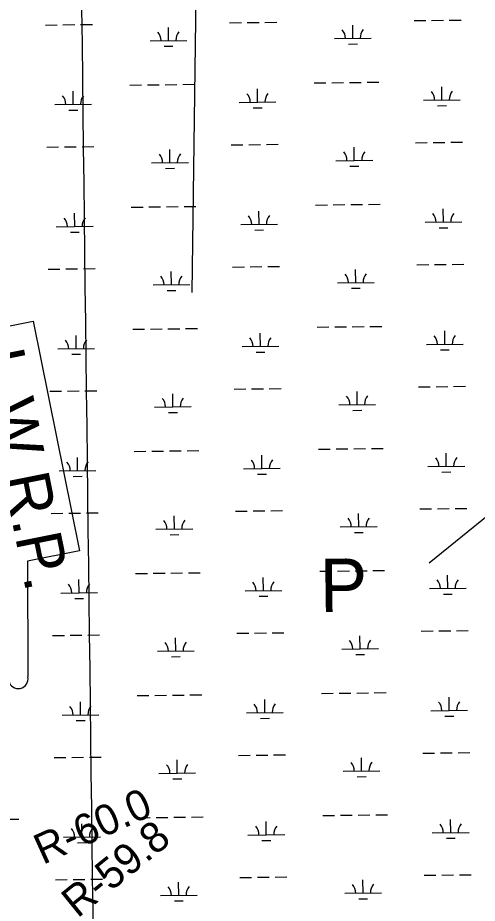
# Model space of a CAD drawing. Extents: x 3694830 to 3732949, y 415201 to 440970.
# Drawn here: x 3720008 to 3721259, y 422124 to 424536 of the extents above; entities that cross this region are included whole.
import ezdxf

# ---------------------------------------------------------------- set-up
doc = ezdxf.new("R2010")
doc.units = 0
for name, color, linetype in [('V-GRID-MAJR', 7, 'Continuous'), ('V-RIVR-RANG-IDEN', 7, 'Continuous'), ('V-TOPO-GNAM-IDEN', 7, 'Continuous'), ('V-TOPO-SHOR', 7, 'Continuous'), ('V-TOPO-WATR-IDEN', 7, 'Continuous'), ('V-WETL-SWMP', 7, 'Continuous')]:
    doc.layers.add(name, color=color, linetype=linetype)

msp = doc.modelspace()

# ---------------------------------------------------------------- linework, layer by layer
at = {"layer": 'V-GRID-MAJR'}
msp.add_spline([(3720228.3, 420868.8), (3720155.2, 426926.1), (3720082, 432986.5), (3720008.8, 439046.9), (3720008.8, 439050)], degree=3, dxfattribs=at)
at = {"layer": 'V-TOPO-SHOR'}
for points in [[(3720482.9, 423787.9), (3720493.7, 424597.8), (3720504.4, 425159.5), (3720510.9, 425652.8), (3720512.1, 425923.1)], [(3721128.3, 423051.5), (3721324.1, 423210), (3721699, 423509.1), (3722006.1, 423752.1)]]:
    msp.add_lwpolyline(points, dxfattribs=at)
at = {"layer": 'V-TOPO-WATR-IDEN'}
msp.add_lwpolyline([(3719789.9, 423962.9), (3719908.3, 423681.4), (3720050.2, 423709.9), (3720175.9, 423083.8), (3720034, 423055.3), (3720035.4, 422740.2)], dxfattribs=at)
msp.add_arc((3720009.4, 422735), 26.5, 191.3511, 11.3511, dxfattribs=at)
at = {"layer": 'V-WETL-SWMP'}
for p, q in [((3720083, 424516.4), (3720115, 424516.8)), ((3720131, 424517), (3720163, 424517.4)), ((3720179, 424517.6), (3720211, 424518)), ((3720584.8, 424522.4), (3720616.8, 424522.8)), ((3720632.8, 424523), (3720664.8, 424523.4)), ((3720680.8, 424523.6), (3720712.8, 424523.9)), ((3720920.2, 424480), (3720919.8, 424516)), ((3721086.7, 424528.4), (3721118.7, 424528.8)), ((3721134.7, 424529), (3721166.7, 424529.4)), ((3721182.7, 424529.6), (3721214.7, 424529.9)), ((3720418.3, 424474), (3720417.9, 424510)), ((3720368.3, 424473.4), (3720468.3, 424474.6)), ((3720870.2, 424479.4), (3720970.2, 424480.6)), ((3720908.4, 424464.4), (3720932.4, 424464.7)), ((3720406.5, 424458.4), (3720430.5, 424458.7)), ((3720312.9, 424352.7), (3720344.9, 424353)), ((3720360.9, 424353.2), (3720392.9, 424353.6)), ((3720408.9, 424353.8), (3720440.9, 424354.2)), ((3720456.9, 424354.4), (3720488.9, 424354.8)), ((3720660.8, 424306.1), (3720660.4, 424342.1)), ((3720814.8, 424358.7), (3720846.8, 424359)), ((3720862.8, 424359.2), (3720894.8, 424359.6)), ((3720910.8, 424359.8), (3720942.8, 424360.2)), ((3720958.8, 424360.4), (3720990.8, 424360.8)), ((3721162.7, 424312.1), (3721162.3, 424348.1)), ((3720159, 424300.1), (3720158.5, 424336.1)), ((3720109, 424299.5), (3720209, 424300.7)), ((3720610.8, 424305.5), (3720710.8, 424306.7)), ((3721112.7, 424311.5), (3721212.7, 424312.7)), ((3721150.9, 424296.5), (3721174.9, 424296.8)), ((3720147.1, 424284.5), (3720171.1, 424284.8)), ((3720649, 424290.5), (3720673, 424290.8)), ((3721138.7, 424196.3), (3721170.7, 424196.7)), ((3721186.7, 424196.9), (3721218.7, 424197.3)), ((3720086.9, 424183.8), (3720118.9, 424184.2)), ((3720134.9, 424184.4), (3720166.9, 424184.7)), ((3720182.9, 424184.9), (3720214.9, 424185.3)), ((3720422.3, 424141.4), (3720421.9, 424177.3)), ((3720588.8, 424189.8), (3720620.8, 424190.2)), ((3720636.8, 424190.3), (3720668.8, 424190.7)), ((3720684.8, 424190.9), (3720716.8, 424191.3)), ((3720924.2, 424147.3), (3720923.7, 424183.3)), ((3721090.7, 424195.8), (3721122.7, 424196.1)), ((3720372.3, 424140.8), (3720472.3, 424141.9)), ((3720410.5, 424125.8), (3720434.5, 424126.1)), ((3720874.2, 424146.7), (3720974.2, 424147.9)), ((3720912.4, 424131.8), (3720936.4, 424132.1)), ((3720914.8, 424027.1), (3720946.8, 424027.5)), ((3720962.8, 424027.7), (3720994.8, 424028.1)), ((3720162.9, 423967.4), (3720162.5, 424003.4)), ((3720316.9, 424020), (3720348.9, 424020.4)), ((3720364.9, 424020.6), (3720396.9, 424021)), ((3720412.9, 424021.2), (3720444.9, 424021.5)), ((3720460.9, 424021.7), (3720492.9, 424022.1)), ((3720664.8, 423973.4), (3720664.4, 424009.4)), ((3720818.8, 424026), (3720850.8, 424026.4)), ((3720866.8, 424026.6), (3720898.8, 424027)), ((3721166.7, 423979.4), (3721166.2, 424015.4)), ((3721116.7, 423978.8), (3721216.7, 423980)), ((3720112.9, 423966.8), (3720212.9, 423968)), ((3720614.8, 423972.8), (3720714.8, 423974)), ((3720653, 423957.8), (3720677, 423958.1)), ((3721154.9, 423963.8), (3721178.9, 423964.1)), ((3720151.1, 423951.9), (3720175.1, 423952.1)), ((3720688.8, 423858.3), (3720720.8, 423858.6)), ((3721094.6, 423863.1), (3721126.6, 423863.5)), ((3721142.6, 423863.7), (3721174.6, 423864.1)), ((3721190.6, 423864.2), (3721222.6, 423864.6)), ((3720090.9, 423851.1), (3720122.9, 423851.5)), ((3720138.9, 423851.7), (3720170.9, 423852.1)), ((3720186.9, 423852.3), (3720218.9, 423852.7)), ((3720426.3, 423808.7), (3720425.8, 423844.7)), ((3720592.8, 423857.1), (3720624.8, 423857.5)), ((3720640.8, 423857.7), (3720672.8, 423858.1)), ((3720928.1, 423814.7), (3720927.7, 423850.7)), ((3720878.1, 423814.1), (3720978.1, 423815.3)), ((3720376.3, 423808.1), (3720476.3, 423809.3)), ((3720414.5, 423793.1), (3720438.5, 423793.4)), ((3720916.3, 423799.1), (3720940.3, 423799.4)), ((3720822.7, 423693.3), (3720854.7, 423693.7)), ((3720870.7, 423693.9), (3720902.7, 423694.3)), ((3720918.7, 423694.5), (3720950.7, 423694.9)), ((3720966.7, 423695.1), (3720998.7, 423695.4)), ((3720166.9, 423634.8), (3720166.5, 423670.8)), ((3720320.9, 423687.4), (3720352.9, 423687.7)), ((3720368.9, 423687.9), (3720400.9, 423688.3)), ((3720416.9, 423688.5), (3720448.9, 423688.9)), ((3720464.9, 423689.1), (3720496.9, 423689.5)), ((3720668.8, 423640.8), (3720668.3, 423676.8)), ((3721170.6, 423646.8), (3721170.2, 423682.8)), ((3721120.6, 423646.2), (3721220.6, 423647.3)), ((3720116.9, 423634.2), (3720216.9, 423635.4)), ((3720155.1, 423619.2), (3720179.1, 423619.5)), ((3720618.8, 423640.2), (3720718.8, 423641.4)), ((3720657, 423625.2), (3720680.9, 423625.5)), ((3721158.8, 423631.2), (3721182.8, 423631.5)), ((3720596.7, 423524.5), (3720628.7, 423524.8)), ((3720644.7, 423525), (3720676.7, 423525.4)), ((3720692.7, 423525.6), (3720724.7, 423526)), ((3721098.6, 423530.5), (3721130.6, 423530.8)), ((3721146.6, 423531), (3721178.6, 423531.4)), ((3721194.6, 423531.6), (3721226.6, 423532)), ((3720094.9, 423518.5), (3720126.9, 423518.9)), ((3720142.9, 423519.1), (3720174.9, 423519.4)), ((3720190.9, 423519.6), (3720222.9, 423520)), ((3720430.2, 423476), (3720429.8, 423512)), ((3720932.1, 423482), (3720931.7, 423518)), ((3720380.2, 423475.5), (3720480.2, 423476.6)), ((3720882.1, 423481.4), (3720982.1, 423482.6)), ((3720418.4, 423460.5), (3720442.4, 423460.8)), ((3720920.3, 423466.5), (3720944.3, 423466.7)), ((3720324.8, 423354.7), (3720356.8, 423355.1)), ((3720372.8, 423355.3), (3720404.8, 423355.7)), ((3720420.8, 423355.9), (3720452.8, 423356.2)), ((3720468.8, 423356.4), (3720500.8, 423356.8)), ((3720826.7, 423360.7), (3720858.7, 423361.1)), ((3720874.7, 423361.3), (3720906.7, 423361.7)), ((3720922.7, 423361.8), (3720954.7, 423362.2)), ((3720970.7, 423362.4), (3721002.7, 423362.8)), ((3720170.9, 423302.1), (3720170.4, 423338.1)), ((3720672.7, 423308.1), (3720672.3, 423344.1)), ((3721174.6, 423314.1), (3721174.2, 423350.1)), ((3720622.7, 423307.5), (3720722.7, 423308.7)), ((3721124.6, 423313.5), (3721224.6, 423314.7)), ((3720120.9, 423301.5), (3720220.9, 423302.7)), ((3720159, 423286.6), (3720183, 423286.8)), ((3720660.9, 423292.5), (3720684.9, 423292.8)), ((3721162.8, 423298.5), (3721186.8, 423298.8)), ((3720098.8, 423185.8), (3720130.8, 423186.2)), ((3720146.8, 423186.4), (3720178.8, 423186.8)), ((3720194.8, 423187), (3720226.8, 423187.4)), ((3720600.7, 423191.8), (3720632.7, 423192.2)), ((3720648.7, 423192.4), (3720680.7, 423192.8)), ((3720696.7, 423193), (3720728.7, 423193.3)), ((3720936.1, 423149.4), (3720935.7, 423185.4)), ((3721102.6, 423197.8), (3721134.6, 423198.2)), ((3721150.6, 423198.4), (3721182.6, 423198.8)), ((3721198.6, 423198.9), (3721230.6, 423199.3)), ((3720434.2, 423143.4), (3720433.8, 423179.4)), ((3720384.2, 423142.8), (3720484.2, 423144)), ((3720886.1, 423148.8), (3720986.1, 423150)), ((3720422.4, 423127.8), (3720446.4, 423128.1)), ((3720924.3, 423133.8), (3720948.3, 423134.1)), ((3720328.8, 423022.1), (3720360.8, 423022.4)), ((3720376.8, 423022.6), (3720408.8, 423023)), ((3720424.8, 423023.2), (3720456.8, 423023.6)), ((3720472.8, 423023.8), (3720504.8, 423024.2)), ((3720830.7, 423028), (3720862.7, 423028.4)), ((3720878.7, 423028.6), (3720910.7, 423029)), ((3720926.7, 423029.2), (3720958.7, 423029.6)), ((3720974.7, 423029.8), (3721006.7, 423030.1)), ((3721178.6, 422981.5), (3721178.1, 423017.4)), ((3720174.8, 422969.5), (3720174.4, 423005.5)), ((3720676.7, 422975.5), (3720676.3, 423011.5)), ((3720124.8, 422968.9), (3720224.8, 422970.1)), ((3720626.7, 422974.9), (3720726.7, 422976.1)), ((3721128.6, 422980.9), (3721228.6, 422982)), ((3721166.8, 422965.9), (3721190.8, 422966.2)), ((3720163, 422953.9), (3720187, 422954.2)), ((3720664.9, 422959.9), (3720688.9, 422960.2)), ((3720102.8, 422853.2), (3720134.8, 422853.6)), ((3720150.8, 422853.8), (3720182.8, 422854.1)), ((3720198.8, 422854.3), (3720230.8, 422854.7)), ((3720438.2, 422810.7), (3720437.7, 422846.7)), ((3720604.7, 422859.2), (3720636.7, 422859.5)), ((3720652.7, 422859.7), (3720684.7, 422860.1)), ((3720700.7, 422860.3), (3720732.7, 422860.7)), ((3720940, 422816.7), (3720939.6, 422852.7)), ((3721106.5, 422865.2), (3721138.5, 422865.5)), ((3721154.5, 422865.7), (3721186.5, 422866.1)), ((3721202.5, 422866.3), (3721234.5, 422866.7)), ((3720388.2, 422810.1), (3720488.2, 422811.3)), ((3720890.1, 422816.1), (3720990, 422817.3)), ((3720928.2, 422801.2), (3720952.2, 422801.4)), ((3720426.4, 422795.2), (3720450.4, 422795.5)), ((3720332.8, 422689.4), (3720364.8, 422689.8)), ((3720380.8, 422690), (3720412.8, 422690.4)), ((3720428.8, 422690.6), (3720460.8, 422690.9)), ((3720476.8, 422691.1), (3720508.8, 422691.5)), ((3720680.7, 422642.8), (3720680.2, 422678.8)), ((3720834.6, 422695.4), (3720866.6, 422695.8)), ((3720882.6, 422696), (3720914.6, 422696.3)), ((3720930.6, 422696.5), (3720962.6, 422696.9)), ((3720978.6, 422697.1), (3721010.6, 422697.5)), ((3721182.5, 422648.8), (3721182.1, 422684.8)), ((3720178.8, 422636.8), (3720178.4, 422672.8)), ((3720128.8, 422636.2), (3720228.8, 422637.4)), ((3720630.7, 422642.2), (3720730.7, 422643.4)), ((3721132.5, 422648.2), (3721232.5, 422649.4)), ((3721170.7, 422633.2), (3721194.7, 422633.5)), ((3720167, 422621.3), (3720191, 422621.5)), ((3720668.9, 422627.2), (3720692.9, 422627.5)), ((3721110.5, 422532.5), (3721142.5, 422532.9)), ((3721158.5, 422533.1), (3721190.5, 422533.5)), ((3721206.5, 422533.6), (3721238.5, 422534)), ((3720106.8, 422520.5), (3720138.8, 422520.9)), ((3720154.8, 422521.1), (3720186.8, 422521.5)), ((3720202.8, 422521.7), (3720234.8, 422522.1)), ((3720442.1, 422478.1), (3720441.7, 422514.1)), ((3720608.6, 422526.5), (3720640.6, 422526.9)), ((3720656.6, 422527.1), (3720688.6, 422527.5)), ((3720704.6, 422527.7), (3720736.6, 422528)), ((3720944, 422484.1), (3720943.6, 422520.1)), ((3720894, 422483.5), (3720994, 422484.7)), ((3720392.1, 422477.5), (3720492.1, 422478.7)), ((3720430.3, 422462.5), (3720454.3, 422462.8)), ((3720932.2, 422468.5), (3720956.2, 422468.8)), ((3720838.6, 422362.7), (3720870.6, 422363.1)), ((3720886.6, 422363.3), (3720918.6, 422363.7)), ((3720934.6, 422363.9), (3720966.6, 422364.3)), ((3720982.6, 422364.5), (3721014.6, 422364.8)), ((3719978.9, 422352.5), (3720010.9, 422352.9)), ((3720182.8, 422304.2), (3720182.3, 422340.2)), ((3720336.7, 422356.8), (3720368.7, 422357.1)), ((3720384.7, 422357.3), (3720416.7, 422357.7)), ((3720432.7, 422357.9), (3720464.7, 422358.3)), ((3720480.7, 422358.5), (3720512.7, 422358.9)), ((3720684.6, 422310.2), (3720684.2, 422346.2)), ((3721186.5, 422316.1), (3721186.1, 422352.1)), ((3721136.5, 422315.6), (3721236.5, 422316.7)), ((3720132.8, 422303.6), (3720232.8, 422304.8)), ((3720634.6, 422309.6), (3720734.6, 422310.8)), ((3720672.8, 422294.6), (3720696.8, 422294.9)), ((3721174.7, 422300.6), (3721198.7, 422300.9)), ((3720170.9, 422288.6), (3720194.9, 422288.9)), ((3720612.6, 422193.9), (3720644.6, 422194.2)), ((3720660.6, 422194.4), (3720692.6, 422194.8)), ((3720708.6, 422195), (3720740.6, 422195.4)), ((3721114.5, 422199.8), (3721146.5, 422200.2)), ((3721162.5, 422200.4), (3721194.5, 422200.8)), ((3721210.5, 422201), (3721242.5, 422201.4)), ((3720110.7, 422187.9), (3720142.7, 422188.3)), ((3720158.7, 422188.4), (3720190.7, 422188.8)), ((3720206.7, 422189), (3720238.7, 422189.4)), ((3720446.1, 422145.4), (3720445.7, 422181.4)), ((3720948, 422151.4), (3720947.6, 422187.4)), ((3720396.1, 422144.8), (3720496.1, 422146)), ((3720898, 422150.8), (3720998, 422152)), ((3720434.3, 422129.9), (3720458.3, 422130.2)), ((3720936.2, 422135.9), (3720960.2, 422136.1))]:
    msp.add_line(p, q, dxfattribs=at)
for centre, start, end in [((3720363.1, 424473.8), 359.9115, 41.4552), ((3720473.6, 424475.1), 139.9115, 181.4552), ((3720865, 424479.8), 359.9115, 41.4552), ((3720975.4, 424481.1), 139.9115, 181.4552), ((3720103.7, 424299.9), 359.9115, 41.4552), ((3720214.2, 424301.2), 139.9115, 181.4552), ((3720605.6, 424305.9), 359.9115, 41.4552), ((3720716.1, 424307.2), 139.9115, 181.4552), ((3721107.5, 424311.9), 359.9115, 41.4552), ((3721217.9, 424313.2), 139.9115, 181.4552), ((3720367.1, 424141.2), 359.9115, 41.4552), ((3720477.5, 424142.5), 139.9115, 181.4552), ((3720868.9, 424147.2), 359.9115, 41.4552), ((3720979.4, 424148.5), 139.9115, 181.4552), ((3720107.7, 423967.2), 359.9115, 41.4552), ((3720218.2, 423968.6), 139.9115, 181.4552), ((3720609.6, 423973.2), 359.9115, 41.4552), ((3720720, 423974.6), 139.9115, 181.4552), ((3721111.4, 423979.2), 359.9115, 41.4552), ((3721221.9, 423980.5), 139.9115, 181.4552), ((3720872.9, 423814.5), 359.9115, 41.4552), ((3720983.4, 423815.8), 139.9115, 181.4552), ((3720371, 423808.5), 359.9115, 41.4552), ((3720481.5, 423809.8), 139.9115, 181.4552), ((3721115.4, 423646.6), 359.9115, 41.4552), ((3721225.9, 423647.9), 139.9115, 181.4552), ((3720111.6, 423634.6), 359.9115, 41.4552), ((3720222.1, 423635.9), 139.9115, 181.4552), ((3720613.5, 423640.6), 359.9115, 41.4552), ((3720724, 423641.9), 139.9115, 181.4552), ((3720375, 423475.9), 359.9115, 41.4552), ((3720485.5, 423477.2), 139.9115, 181.4552), ((3720876.9, 423481.9), 359.9115, 41.4552), ((3720987.3, 423483.2), 139.9115, 181.4552), ((3720617.5, 423307.9), 359.9115, 41.4552), ((3720728, 423309.2), 139.9115, 181.4552), ((3721119.4, 423313.9), 359.9115, 41.4552), ((3721229.8, 423315.2), 139.9115, 181.4552), ((3720115.6, 423301.9), 359.9115, 41.4552), ((3720226.1, 423303.3), 139.9115, 181.4552), ((3720379, 423143.2), 359.9115, 41.4552), ((3720489.4, 423144.5), 139.9115, 181.4552), ((3720880.8, 423149.2), 359.9115, 41.4552), ((3720991.3, 423150.5), 139.9115, 181.4552), ((3720119.6, 422969.3), 359.9115, 41.4552), ((3720230.1, 422970.6), 139.9115, 181.4552), ((3720621.5, 422975.3), 359.9115, 41.4552), ((3720731.9, 422976.6), 139.9115, 181.4552), ((3721123.3, 422981.3), 359.9115, 41.4552), ((3721233.8, 422982.6), 139.9115, 181.4552), ((3720382.9, 422810.6), 359.9115, 41.4552), ((3720493.4, 422811.9), 139.9115, 181.4552), ((3720884.8, 422816.5), 359.9115, 41.4552), ((3720995.3, 422817.9), 139.9115, 181.4552), ((3720123.6, 422636.6), 359.9115, 41.4552), ((3720234, 422638), 139.9115, 181.4552), ((3720625.4, 422642.6), 359.9115, 41.4552), ((3720735.9, 422643.9), 139.9115, 181.4552), ((3721127.3, 422648.6), 359.9115, 41.4552), ((3721237.8, 422649.9), 139.9115, 181.4552), ((3720999.2, 422485.2), 139.9115, 181.4552), ((3720386.9, 422477.9), 359.9115, 41.4552), ((3720497.4, 422479.2), 139.9115, 181.4552), ((3720888.8, 422483.9), 359.9115, 41.4552), ((3721131.3, 422316), 359.9115, 41.4552), ((3721241.7, 422317.3), 139.9115, 181.4552), ((3720127.5, 422304), 359.9115, 41.4552), ((3720238, 422305.3), 139.9115, 181.4552), ((3720629.4, 422310), 359.9115, 41.4552), ((3720739.9, 422311.3), 139.9115, 181.4552), ((3720892.7, 422151.2), 359.9115, 41.4552), ((3721003.2, 422152.6), 139.9115, 181.4552), ((3720390.9, 422145.3), 359.9115, 41.4552), ((3720501.3, 422146.6), 139.9115, 181.4552)]:
    msp.add_arc(centre, 35.2, start, end, dxfattribs=at)

# ---------------------------------------------------------------- texts
at = {"layer": 'V-RIVR-RANG-IDEN'}
for s, rotation, p in [('R-60.0', 24.3506, (3720076.4, 422227.8)), ('R-59.8', 39.0127, (3720170.5, 422081.4))]:
    msp.add_text(s, height=83, rotation=rotation, dxfattribs=at).set_placement(p)
at = {"layer": 'V-TOPO-GNAM-IDEN'}
msp.add_text('P', height=145, rotation=0.7812, dxfattribs=at).set_placement((3720830.9, 422917))
at = {"layer": 'V-TOPO-WATR-IDEN'}
msp.add_text('L.W.R.P.', height=124.5, rotation=281.351, dxfattribs=at).set_placement((3719900.4, 423620.9))

doc.saveas('drawing.dxf')
